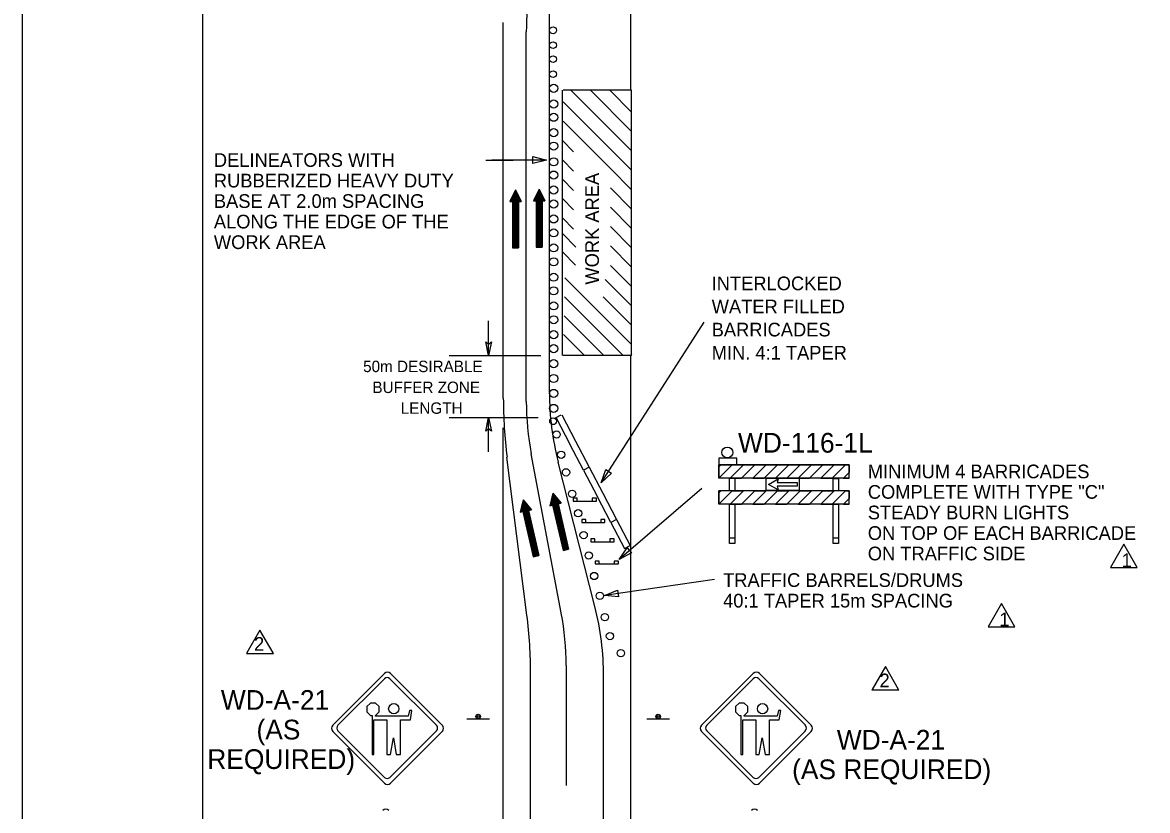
# Model space of a CAD drawing. Extents: x 2170 to 2386, y 134 to 413.
# Drawn here: x 2169.6 to 2288.9, y 273.1 to 356.6 of the extents above; entities that cross this region are included whole.
import ezdxf

# ---------------------------------------------------------------- set-up
doc = ezdxf.new("R2010")
doc.units = 0
for name, color, linetype in [('Level 1', 7, 'Continuous'), ('Level 10', 7, 'Continuous'), ('Level 20', 7, 'Continuous'), ('Level 4', 7, 'Continuous'), ('Level 44', 7, 'Continuous'), ('Level 5', 7, 'Continuous'), ('Level 60', 7, 'Continuous'), ('Level 63', 7, 'Continuous')]:
    doc.layers.add(name, color=color, linetype=linetype)

# ---------------------------------------------------------------- blocks, each defined once
blk = doc.blocks.new('TAH01')
at = {"layer": 'Level 5'}
blk.add_lwpolyline([(0, 0), (-3, -0.62), (-2.504, 0), (-3, 0.62)], close=True, dxfattribs=at)
blk = doc.blocks.new('LT1')
at = {"layer": 'Level 5'}
blk.add_blockref('TAH01', (0, 0), dxfattribs=at)
blk = doc.blocks.new('REV1')
at = {"layer": 'Level 1'}
blk.add_lwpolyline([(0.114, 1.689), (-1.305, -0.781), (1.533, -0.781)], close=True, dxfattribs=at)
blk.add_text('1', height=1.448, rotation=360, dxfattribs=at).set_placement((-0.113, -0.724))

msp = doc.modelspace()

# ---------------------------------------------------------------- linework, layer by layer
at = {"layer": 'Level 1'}
for p, q in [((2206.52, 284.45), (2206.14, 284.07)), ((2206.14, 284.07), (2206.14, 283.53)), ((2207.06, 284.45), (2206.52, 284.45)), ((2207.45, 284.07), (2207.06, 284.45)), ((2207.45, 283.53), (2207.45, 284.07)), ((2245.64, 284.45), (2245.26, 284.07)), ((2245.26, 284.07), (2245.26, 283.53)), ((2246.18, 284.45), (2245.64, 284.45)), ((2246.57, 284.07), (2246.18, 284.45)), ((2246.57, 283.53), (2246.57, 284.07)), ((2206.14, 283.53), (2206.52, 283.14)), ((2206.52, 283.14), (2206.7, 283.14)), ((2206.7, 283.14), (2206.7, 278.99)), ((2207.06, 283.14), (2207.45, 283.53)), ((2207.06, 283.07), (2207.06, 283.14)), ((2210.54, 283.07), (2207.06, 283.07)), ((2210.68, 283.66), (2210.54, 283.07)), ((2210.92, 283.66), (2210.68, 283.66)), ((2210.77, 282.68), (2210.92, 283.66)), ((2245.26, 283.53), (2245.64, 283.14)), ((2245.64, 283.14), (2245.82, 283.14)), ((2245.82, 283.14), (2245.82, 278.99)), ((2246.18, 283.14), (2246.57, 283.53)), ((2246.18, 283.07), (2246.18, 283.14)), ((2249.66, 283.07), (2246.18, 283.07)), ((2249.8, 283.66), (2249.66, 283.07)), ((2250.04, 283.66), (2249.8, 283.66)), ((2249.89, 282.68), (2250.04, 283.66)), ((2206.89, 278.99), (2206.89, 282.68)), ((2206.89, 282.68), (2208.27, 282.68)), ((2208.27, 282.68), (2208.27, 278.99)), ((2209.72, 278.99), (2209.72, 282.68)), ((2209.72, 282.68), (2210.77, 282.68)), ((2246.01, 278.99), (2246.01, 282.68)), ((2246.01, 282.68), (2247.39, 282.68)), ((2247.39, 282.68), (2247.39, 278.99)), ((2248.84, 278.99), (2248.84, 282.68)), ((2248.84, 282.68), (2249.89, 282.68)), ((2208.64, 278.99), (2208.96, 280.76)), ((2208.96, 280.76), (2209.27, 278.99)), ((2247.76, 278.99), (2248.08, 280.76)), ((2248.08, 280.76), (2248.39, 278.99)), ((2206.7, 278.99), (2206.89, 278.99)), ((2208.27, 278.99), (2208.64, 278.99)), ((2209.27, 278.99), (2209.72, 278.99)), ((2245.82, 278.99), (2246.01, 278.99)), ((2247.39, 278.99), (2247.76, 278.99)), ((2248.39, 278.99), (2248.84, 278.99))]:
    msp.add_line(p, q, dxfattribs=at)
for centre in [(2209, 283.85), (2248.12, 283.85)]:
    msp.add_circle(centre, 0.544, dxfattribs=at)
at = {"layer": 'Level 10'}
for p, q in [((2220.62, 353.23), (2220.62, 356.61)), ((2223.06, 316.44), (2223.06, 355.61)), ((2220.62, 321.3), (2220.62, 353.23)), ((2226.89, 321.3), (2226.89, 349.42)), ((2234.22, 349.42), (2226.96, 349.42)), ((2234.22, 342.99), (2227.79, 349.42)), ((2234.22, 345.04), (2229.85, 349.42)), ((2234.22, 347.09), (2231.9, 349.42)), ((2234.22, 321.3), (2234.22, 349.42)), ((2232.01, 343.15), (2226.96, 348.19)), ((2232.09, 341.02), (2226.96, 346.14)), ((2228.06, 342.91), (2226.89, 344.09)), ((2234.22, 340.94), (2231.98, 343.18)), ((2218.77, 342.02), (2221.68, 342.02)), ((2225.19, 342.02), (2219.39, 342.02)), ((2228.06, 340.86), (2226.89, 342.04)), ((2234.22, 338.88), (2231.98, 341.13)), ((2224.42, 338.92), (2223.81, 337.69)), ((2224.42, 338.92), (2224.42, 332.78)), ((2224.42, 338.92), (2225.03, 337.69)), ((2228.06, 338.81), (2226.89, 339.98)), ((2234.22, 336.83), (2231.98, 339.07)), ((2221.92, 338.85), (2221.3, 337.62)), ((2221.38, 337.78), (2221.38, 337.62)), ((2221.46, 337.93), (2221.46, 337.62)), ((2221.53, 338.08), (2221.53, 337.62)), ((2221.61, 338.24), (2221.61, 332.71)), ((2221.69, 338.39), (2221.69, 332.71)), ((2221.76, 338.54), (2221.76, 332.71)), ((2221.84, 338.7), (2221.84, 332.71)), ((2221.92, 338.85), (2221.92, 332.71)), ((2221.92, 338.85), (2222.53, 337.62)), ((2221.99, 338.7), (2221.99, 332.71)), ((2222.07, 338.54), (2222.07, 332.71)), ((2222.15, 338.39), (2222.15, 332.71)), ((2222.22, 338.24), (2222.22, 332.71)), ((2222.3, 338.08), (2222.3, 337.62)), ((2222.38, 337.93), (2222.38, 337.62)), ((2222.45, 337.78), (2222.45, 337.62)), ((2223.81, 337.69), (2224.12, 337.69)), ((2223.89, 337.84), (2223.89, 337.69)), ((2223.96, 338), (2223.96, 337.69)), ((2224.04, 338.15), (2224.04, 337.69)), ((2224.12, 338.3), (2224.12, 332.78)), ((2224.12, 337.69), (2224.12, 332.78)), ((2224.19, 338.46), (2224.19, 332.78)), ((2224.27, 338.61), (2224.27, 332.78)), ((2224.35, 338.76), (2224.35, 332.78)), ((2224.5, 338.76), (2224.5, 332.78)), ((2224.58, 338.61), (2224.58, 332.78)), ((2224.65, 338.46), (2224.65, 332.78)), ((2224.73, 338.3), (2224.73, 332.78)), ((2224.73, 337.69), (2224.73, 332.78)), ((2224.73, 337.69), (2225.03, 337.69)), ((2224.81, 338.15), (2224.81, 337.69)), ((2224.88, 338), (2224.88, 337.69)), ((2224.96, 337.84), (2224.96, 337.69)), ((2228.06, 336.75), (2226.89, 337.93)), ((2221.3, 337.62), (2221.61, 337.62)), ((2221.61, 337.62), (2221.61, 332.71)), ((2222.22, 337.62), (2222.22, 332.71)), ((2222.22, 337.62), (2222.53, 337.62)), ((2234.22, 334.78), (2231.98, 337.02)), ((2228.06, 334.7), (2226.89, 335.88)), ((2228.32, 332.8), (2226.92, 334.2)), ((2234.22, 332.73), (2231.98, 334.97)), ((2234.22, 330.67), (2231.98, 332.92)), ((2221.61, 332.71), (2222.22, 332.71)), ((2224.12, 332.78), (2224.73, 332.78)), ((2228.28, 330.88), (2226.88, 332.28)), ((2234.22, 328.62), (2231.98, 330.86)), ((2234.22, 322.46), (2227.16, 329.53)), ((2234.22, 326.57), (2231.42, 329.37)), ((2233.32, 321.31), (2227.11, 327.52)), ((2234.22, 324.51), (2231.22, 327.52)), ((2231.25, 321.32), (2227.06, 325.52)), ((2231, 307.81), (2241.94, 324.83)), ((2229.18, 321.34), (2227.02, 323.51)), ((2220.62, 316.78), (2220.62, 321.81)), ((2234.22, 321.3), (2226.96, 321.3)), ((2234.22, 321.39), (2234.13, 321.3)), ((2229.13, 309.14), (2227.68, 311.91)), ((2228.28, 312.23), (2229.73, 309.46)), ((2223.13, 293.76), (2221.01, 310.52)), ((2226.76, 294), (2223.58, 310.88)), ((2230.33, 294.68), (2226.44, 309.98)), ((2229.73, 309.46), (2229.13, 309.14)), ((2225.86, 306.69), (2225.54, 305.36)), ((2225.86, 306.69), (2227.24, 300.71)), ((2225.86, 306.69), (2226.74, 305.63)), ((2231.18, 306.69), (2232.63, 303.91)), ((2222.72, 306.01), (2222.4, 304.68)), ((2222.6, 305.51), (2223.88, 299.98)), ((2222.64, 305.68), (2223.95, 300)), ((2222.68, 305.85), (2224.03, 300.02)), ((2222.72, 306.01), (2224.1, 300.03)), ((2222.72, 306.01), (2223.6, 304.95)), ((2222.83, 305.88), (2224.18, 300.05)), ((2222.94, 305.75), (2224.25, 300.07)), ((2223.05, 305.61), (2224.33, 300.08)), ((2223.16, 305.48), (2224.4, 300.1)), ((2225.58, 305.52), (2225.62, 305.37)), ((2225.62, 305.69), (2225.69, 305.39)), ((2225.66, 305.86), (2225.77, 305.41)), ((2225.7, 306.02), (2226.95, 300.64)), ((2225.74, 306.19), (2227.02, 300.66)), ((2225.78, 306.36), (2227.09, 300.68)), ((2225.82, 306.52), (2227.17, 300.69)), ((2225.97, 306.56), (2227.32, 300.73)), ((2226.08, 306.43), (2227.39, 300.75)), ((2226.19, 306.29), (2227.47, 300.76)), ((2226.3, 306.16), (2227.54, 300.78)), ((2226.41, 306.03), (2226.51, 305.58)), ((2226.44, 305.56), (2226.74, 305.63)), ((2226.44, 305.56), (2227.54, 300.78)), ((2226.52, 305.9), (2226.59, 305.6)), ((2226.63, 305.76), (2226.66, 305.62)), ((2232.03, 303.6), (2230.58, 306.37)), ((2222.4, 304.68), (2222.7, 304.75)), ((2222.44, 304.84), (2222.48, 304.7)), ((2222.48, 305.01), (2222.55, 304.71)), ((2222.52, 305.18), (2222.62, 304.73)), ((2222.56, 305.35), (2223.8, 299.97)), ((2222.7, 304.75), (2223.8, 299.97)), ((2223.27, 305.35), (2223.37, 304.9)), ((2223.3, 304.88), (2223.6, 304.95)), ((2223.3, 304.88), (2224.4, 300.1)), ((2223.38, 305.22), (2223.45, 304.92)), ((2223.49, 305.09), (2223.52, 304.94)), ((2225.54, 305.36), (2225.84, 305.43)), ((2225.84, 305.43), (2226.95, 300.64)), ((2232.63, 303.91), (2232.03, 303.6)), ((2226.95, 300.64), (2227.54, 300.78)), ((2223.8, 299.97), (2224.4, 300.1)), ((2243.03, 297.56), (2231.34, 295.87)), ((2223.52, 177.99), (2223.52, 287.5)), ((2231.26, 177.84), (2231.26, 287.27))]:
    msp.add_line(p, q, dxfattribs=at)
for points in [[(2223.74, 342.39), (2225.19, 342.02), (2223.74, 341.66)], [(2243.47, 309.72), (2245.38, 309.72), (2245.38, 310.41), (2243.47, 310.41)], [(2232.09, 308.83), (2231, 307.81), (2231.48, 309.22)], [(2234.22, 300.37), (2232.9, 299.67), (2233.74, 300.91)], [(2232.83, 295.72), (2231.34, 295.87), (2232.73, 296.43)]]:
    msp.add_lwpolyline(points, close=True, dxfattribs=at)
msp.add_lwpolyline([(2227.28, 288.44), (2227.28, 275.72)], dxfattribs=at)
for centre, radius in [((2225.89, 355.78), 0.359), ((2225.89, 354.2), 0.359), ((2225.89, 352.72), 0.359), ((2225.89, 351.13), 0.359), ((2225.96, 349.63), 0.431), ((2225.96, 347.96), 0.431), ((2225.96, 346.56), 0.431), ((2225.96, 344.92), 0.431), ((2225.96, 343.5), 0.431), ((2225.96, 341.83), 0.431), ((2225.96, 340.43), 0.431), ((2225.96, 338.85), 0.431), ((2225.96, 337.36), 0.431), ((2225.96, 335.78), 0.431), ((2225.96, 334.3), 0.431), ((2225.96, 332.71), 0.431), ((2225.96, 331.23), 0.431), ((2225.96, 329.6), 0.431), ((2225.96, 328.16), 0.431), ((2225.96, 326.56), 0.431), ((2225.96, 325.09), 0.431), ((2225.96, 323.51), 0.431), ((2225.96, 322.03), 0.431), ((2225.96, 320.44), 0.431), ((2225.96, 318.86), 0.431), ((2225.96, 317.28), 0.431), ((2225.96, 315.69), 0.431), ((2225.9, 314.33), 0.359), ((2244.38, 311.02), 0.576)]:
    msp.add_circle(centre, radius, dxfattribs=at)
for centre, radius, start, end in [((2253.06, 355.61), 30, 161.9995, 180), ((2255.51, 317.39), 30, 179.9638, 194.2871), ((2270.62, 316.78), 50, 180, 187.1968), ((2253.06, 316.44), 30, 180, 190.6664), ((2173.52, 287.5), 50, 0, 7.1968), ((2197.28, 288.44), 30, 0, 10.6664), ((2201.26, 287.27), 30, 0, 14.2871)]:
    msp.add_arc(centre, radius, start, end, dxfattribs=at)
at = {"layer": 'Level 20'}
for p, q in [((2234.16, 349.42), (2234.16, 399.31)), ((2234.16, 177.84), (2234.16, 321.3)), ((2226.15, 314.68), (2226.75, 315)), ((2226.22, 314.68), (2227.68, 311.91)), ((2226.82, 315), (2228.28, 312.23)), ((2220.62, 177.82), (2220.62, 313.63)), ((2229.13, 309.14), (2230.58, 306.37)), ((2229.73, 309.46), (2231.18, 306.69)), ((2232.03, 303.6), (2233.48, 300.83)), ((2232.63, 303.91), (2234.09, 301.14)), ((2233.48, 300.83), (2234.09, 301.14))]:
    msp.add_line(p, q, dxfattribs=at)
at = {"layer": 'Level 4'}
msp.add_line((2225.51, 317.4), (2225.53, 358.33), dxfattribs=at)
at = {"layer": 'Level 44'}
for p, q in [((2219.06, 321.3), (2219.06, 324.96)), ((2214.86, 321.3), (2224.59, 321.3)), ((2214.86, 314.73), (2224.33, 314.73)), ((2219.06, 311.07), (2219.06, 314.73)), ((2208.01, 287.58), (2202.52, 282.1)), ((2214.15, 282.1), (2208.66, 287.58)), ((2247.13, 287.58), (2241.64, 282.1)), ((2253.27, 282.1), (2247.78, 287.58)), ((2203.07, 282.09), (2208.01, 287.03)), ((2208.6, 287.03), (2213.54, 282.09)), ((2242.19, 282.09), (2247.13, 287.03)), ((2247.72, 287.03), (2252.66, 282.09)), ((2219.15, 282.75), (2216.76, 282.75)), ((2238.24, 282.75), (2235.84, 282.75)), ((2202.52, 281.45), (2208.01, 275.95)), ((2202.53, 281.45), (2202.52, 281.45)), ((2208.01, 276.57), (2203.07, 281.51)), ((2213.54, 281.51), (2208.6, 276.57)), ((2208.66, 275.95), (2214.15, 281.45)), ((2241.64, 281.45), (2247.13, 275.95)), ((2241.64, 281.45), (2241.64, 281.45)), ((2247.13, 276.57), (2242.19, 281.51)), ((2252.66, 281.51), (2247.72, 276.57)), ((2247.78, 275.95), (2253.27, 281.45))]:
    msp.add_line(p, q, dxfattribs=at)
for centre, radius in [((2217.95, 283.02), 0.24), ((2217.95, 283.02), 0.12), ((2237.04, 283.02), 0.24), ((2237.04, 283.02), 0.12)]:
    msp.add_circle(centre, radius, dxfattribs=at)
for centre, radius, start, end in [((2208.34, 287.26), 0.459, 45, 135), ((2247.46, 287.26), 0.459, 45, 135), ((2208.3, 286.74), 0.413, 45, 135), ((2247.42, 286.74), 0.413, 45, 135), ((2202.85, 281.77), 0.459, 135, 225), ((2203.37, 281.8), 0.413, 135, 225), ((2213.24, 281.8), 0.413, 315, 45), ((2213.83, 281.77), 0.459, 315, 45), ((2241.97, 281.77), 0.459, 135, 225), ((2242.49, 281.8), 0.413, 135, 225), ((2252.36, 281.8), 0.413, 315, 45), ((2252.95, 281.77), 0.459, 315, 45), ((2208.3, 276.86), 0.413, 225, 315), ((2208.34, 276.28), 0.459, 225, 315), ((2247.42, 276.86), 0.413, 225, 315), ((2247.46, 276.28), 0.459, 225, 315), ((2208.15, 272.73), 0.458, 45, 135), ((2247.27, 272.73), 0.458, 45, 135)]:
    msp.add_arc(centre, radius, start, end, dxfattribs=at)
at = {"layer": 'Level 5'}
for p, q in [((2257.31, 309.72), (2243.47, 309.72)), ((2243.47, 308.3), (2243.47, 309.72)), ((2243.47, 309.72), (2257.31, 309.72)), ((2245.74, 309.72), (2246.31, 309.72)), ((2257.31, 308.3), (2257.31, 309.72)), ((2257.31, 308.3), (2243.47, 308.3)), ((2244.61, 308.27), (2244.61, 308.3)), ((2248.52, 308.28), (2252.01, 308.28)), ((2248.52, 308.28), (2252.01, 308.28)), ((2255.61, 308.27), (2255.61, 308.3)), ((2241.68, 307.2), (2232.9, 299.67)), ((2243.47, 305.53), (2243.47, 306.95)), ((2257.31, 306.95), (2243.47, 306.95)), ((2252.01, 306.98), (2248.52, 306.98)), ((2252.01, 306.98), (2248.52, 306.98)), ((2256.18, 306.95), (2255.89, 306.95)), ((2257.31, 305.53), (2257.31, 306.95)), ((2228.46, 306.17), (2228.02, 306.17)), ((2228.02, 306.17), (2228.02, 305.87)), ((2228.02, 305.87), (2230.49, 305.87)), ((2228.46, 305.87), (2228.46, 306.17)), ((2230.49, 306.17), (2230.05, 306.17)), ((2230.05, 306.17), (2230.05, 305.87)), ((2230.49, 305.87), (2230.49, 306.17)), ((2257.31, 305.53), (2243.47, 305.53)), ((2229.38, 303.9), (2228.94, 303.9)), ((2228.94, 303.9), (2228.94, 303.6)), ((2228.94, 303.6), (2231.4, 303.6)), ((2229.38, 303.6), (2229.38, 303.9)), ((2231.4, 303.9), (2230.97, 303.9)), ((2230.97, 303.9), (2230.97, 303.6)), ((2231.4, 303.6), (2231.4, 303.9)), ((2245.17, 301.92), (2244.61, 301.92)), ((2256.18, 301.92), (2255.61, 301.92)), ((2230.34, 301.86), (2229.9, 301.86)), ((2229.9, 301.86), (2229.9, 301.56)), ((2229.9, 301.56), (2232.37, 301.56)), ((2230.34, 301.56), (2230.34, 301.86)), ((2232.37, 301.86), (2231.93, 301.86)), ((2231.93, 301.86), (2231.93, 301.56)), ((2232.37, 301.56), (2232.37, 301.86)), ((2230.8, 299.5), (2230.36, 299.5)), ((2230.36, 299.5), (2230.36, 299.2)), ((2230.8, 299.2), (2230.8, 299.5)), ((2232.83, 299.5), (2232.39, 299.5)), ((2232.39, 299.5), (2232.39, 299.2)), ((2232.83, 299.2), (2232.83, 299.5)), ((2230.36, 299.2), (2232.83, 299.2))]:
    msp.add_line(p, q, dxfattribs=at)
for points in [[(2243.47, 308.3), (2244.89, 309.72), (2243.69, 309.72), (2243.47, 309.5), (2243.47, 308.3)], [(2245.88, 308.3), (2247.3, 309.72), (2246.09, 309.72), (2244.67, 308.3), (2245.88, 308.3)], [(2248.28, 308.3), (2249.7, 309.72), (2248.5, 309.72), (2247.08, 308.3), (2248.28, 308.3)], [(2250.69, 308.3), (2252.11, 309.72), (2250.91, 309.72), (2249.49, 308.3), (2250.69, 308.3)], [(2254.52, 309.72), (2253.31, 309.72), (2251.89, 308.3), (2253.1, 308.3), (2254.52, 309.72)], [(2256.92, 309.72), (2255.72, 309.72), (2254.3, 308.3), (2255.51, 308.3), (2256.92, 309.72)], [(2257.31, 308.9), (2256.71, 308.3), (2257.31, 308.3), (2257.31, 308.9)], [(2243.47, 305.53), (2244.89, 306.95), (2243.69, 306.95), (2243.47, 306.74), (2243.47, 305.53)], [(2245.88, 305.53), (2247.3, 306.95), (2246.09, 306.95), (2244.67, 305.53), (2245.88, 305.53)], [(2248.28, 305.53), (2249.7, 306.95), (2248.5, 306.95), (2247.08, 305.53), (2248.28, 305.53)], [(2250.69, 305.53), (2252.11, 306.95), (2250.91, 306.95), (2249.49, 305.53), (2250.69, 305.53)], [(2254.52, 306.95), (2253.31, 306.95), (2251.89, 305.53), (2253.1, 305.53), (2254.52, 306.95)], [(2256.92, 306.95), (2255.72, 306.95), (2254.3, 305.53), (2255.51, 305.53), (2256.92, 306.95)], [(2257.31, 306.14), (2256.71, 305.53), (2257.31, 305.53), (2257.31, 306.14)]]:
    msp.add_lwpolyline(points, dxfattribs=at)
for points in [[(2244.89, 309.72), (2246.09, 309.72), (2244.67, 308.3), (2243.47, 308.3)], [(2243.69, 309.72), (2243.47, 309.72), (2243.47, 309.5)], [(2247.3, 309.72), (2248.5, 309.72), (2247.08, 308.3), (2245.88, 308.3)], [(2249.7, 309.72), (2250.91, 309.72), (2249.49, 308.3), (2248.28, 308.3)], [(2252.11, 309.72), (2253.31, 309.72), (2251.89, 308.3), (2250.69, 308.3)], [(2254.52, 309.72), (2255.72, 309.72), (2254.3, 308.3), (2253.1, 308.3)], [(2256.92, 309.72), (2257.31, 309.72), (2257.31, 308.9), (2256.71, 308.3), (2255.51, 308.3)], [(2244.61, 308.27), (2245.17, 308.3), (2245.17, 306.95), (2244.61, 306.95)], [(2252.01, 308.28), (2252.01, 306.95), (2248.5, 306.95), (2248.5, 308.28)], [(2251.79, 307.82), (2251.79, 307.44), (2249.66, 307.44), (2249.77, 307.05), (2248.75, 307.63), (2249.77, 308.22), (2249.66, 307.82)], [(2255.61, 308.27), (2256.18, 308.27), (2256.18, 306.95), (2255.61, 306.95)], [(2243.47, 306.95), (2243.69, 306.95), (2243.47, 306.74)], [(2244.89, 306.95), (2246.09, 306.95), (2244.67, 305.53), (2243.47, 305.53)], [(2247.3, 306.95), (2248.5, 306.95), (2247.08, 305.53), (2245.88, 305.53)], [(2249.7, 306.95), (2250.91, 306.95), (2249.49, 305.53), (2248.28, 305.53)], [(2252.11, 306.95), (2253.31, 306.95), (2251.89, 305.53), (2250.69, 305.53)], [(2254.52, 306.95), (2255.72, 306.95), (2254.3, 305.53), (2253.1, 305.53)], [(2256.92, 306.95), (2257.31, 306.95), (2257.31, 306.14), (2256.71, 305.53), (2255.51, 305.53)], [(2244.61, 305.52), (2245.17, 305.52), (2245.17, 301.35), (2244.61, 301.35)], [(2255.61, 305.52), (2256.18, 305.52), (2256.18, 301.35), (2255.61, 301.35)]]:
    msp.add_lwpolyline(points, close=True, dxfattribs=at)
for centre in [(2226.27, 312.93), (2226.75, 310.78), (2227.27, 308.91), (2227.93, 306.63), (2228.56, 304.57), (2229.14, 302.26), (2229.68, 300.1), (2230.26, 297.92), (2230.85, 295.82), (2231.39, 293.56), (2231.93, 291.55), (2233.08, 289.74)]:
    msp.add_circle(centre, 0.388, dxfattribs=at)
at = {"layer": 'Level 60'}
for points in [[(2169.62, 412.76), (2385.62, 412.76), (2385.62, 133.76), (2169.62, 133.76)], [(2188.75, 401.95), (2375.62, 401.95), (2375.62, 144.57), (2188.75, 144.57)]]:
    msp.add_lwpolyline(points, close=True, dxfattribs=at)
at = {"layer": 'Level 63'}
for points in [[(2194.81, 292.19), (2193.41, 289.77)], [(2196.2, 289.77), (2194.81, 292.19)], [(2193.41, 289.77), (2193.39, 289.72), (2196.23, 289.72), (2196.2, 289.77)], [(2261.14, 288.32), (2259.75, 285.9)], [(2262.54, 285.9), (2261.14, 288.32)], [(2259.75, 285.9), (2259.72, 285.85), (2262.56, 285.85), (2262.54, 285.9)]]:
    msp.add_lwpolyline(points, dxfattribs=at)

# ---------------------------------------------------------------- block references
at = {"layer": 'Level 1'}
for p in [(2286.31, 299.59), (2273.35, 293.32)]:
    msp.add_blockref('REV1', p, dxfattribs=at)
at = {"layer": 'Level 5', "xscale": 0.4838, "yscale": 0.4838}
for p, rotation in [((2219.06, 321.3), -90), ((2219.06, 314.73), 90)]:
    msp.add_blockref('LT1', p, dxfattribs=dict(at, rotation=rotation))

# ---------------------------------------------------------------- texts
at = {"layer": 'Level 10'}
for s, height, p in [('DELINEATORS WITH ', 1.451, (2189.92, 341.3)), ('RUBBERIZED HEAVY DUTY ', 1.451, (2189.92, 339.12)), ('BASE AT 2.0m SPACING ', 1.451, (2189.92, 336.95)), ('ALONG THE EDGE OF THE ', 1.451, (2189.92, 334.77)), ('WORK AREA', 1.451, (2189.92, 332.59)), ('INTERLOCKED', 1.451, (2242.72, 328.22)), ('WATER FILLED', 1.451, (2242.72, 325.77)), ('BARRICADES', 1.451, (2242.72, 323.32)), ('MIN. 4:1 TAPER', 1.451, (2242.72, 320.87)), ('WD-116-1L', 2.09, (2245.51, 311)), ('MINIMUM 4 BARRICADES', 1.4514, (2259.28, 308.28)), ('COMPLETE WITH TYPE "C" ', 1.4514, (2259.28, 306.11)), ('STEADY BURN LIGHTS', 1.4514, (2259.28, 303.93)), ('ON TOP OF EACH BARRICADE ', 1.4514, (2259.28, 301.75)), ('ON TRAFFIC SIDE', 1.4514, (2259.28, 299.58)), ('TRAFFIC BARRELS/DRUMS ', 1.4514, (2243.93, 296.76)), ('40:1 TAPER 15m SPACING', 1.4514, (2243.93, 294.58)), ('WD-A-21', 2.09, (2190.66, 283.73)), ('(AS ', 2.09, (2194.44, 280.59)), ('WD-A-21', 2.09, (2255.99, 279.51)), ('REQUIRED)', 2.09, (2189.22, 277.46)), ('(AS REQUIRED)', 2.09, (2251.25, 276.38))]:
    msp.add_text(s, height=height, dxfattribs=at).set_placement(p)
msp.add_text('WORK AREA', height=1.451, rotation=90, dxfattribs=at).set_placement((2230.76, 328.81))
at = {"layer": 'Level 44'}
for s, height, p in [('50m DESIRABLE', 1.2095, (2205.75, 319.54)), ('BUFFER ZONE', 1.2095, (2206.74, 317.32)), ('LENGTH', 1.209, (2209.74, 315.12))]:
    msp.add_text(s, height=height, dxfattribs=at).set_placement(p)
for p in [(2194.18, 289.99), (2260.52, 286.12)]:
    msp.add_text('2', height=1.45, rotation=360, dxfattribs=at).set_placement(p)

doc.saveas('drawing.dxf')
